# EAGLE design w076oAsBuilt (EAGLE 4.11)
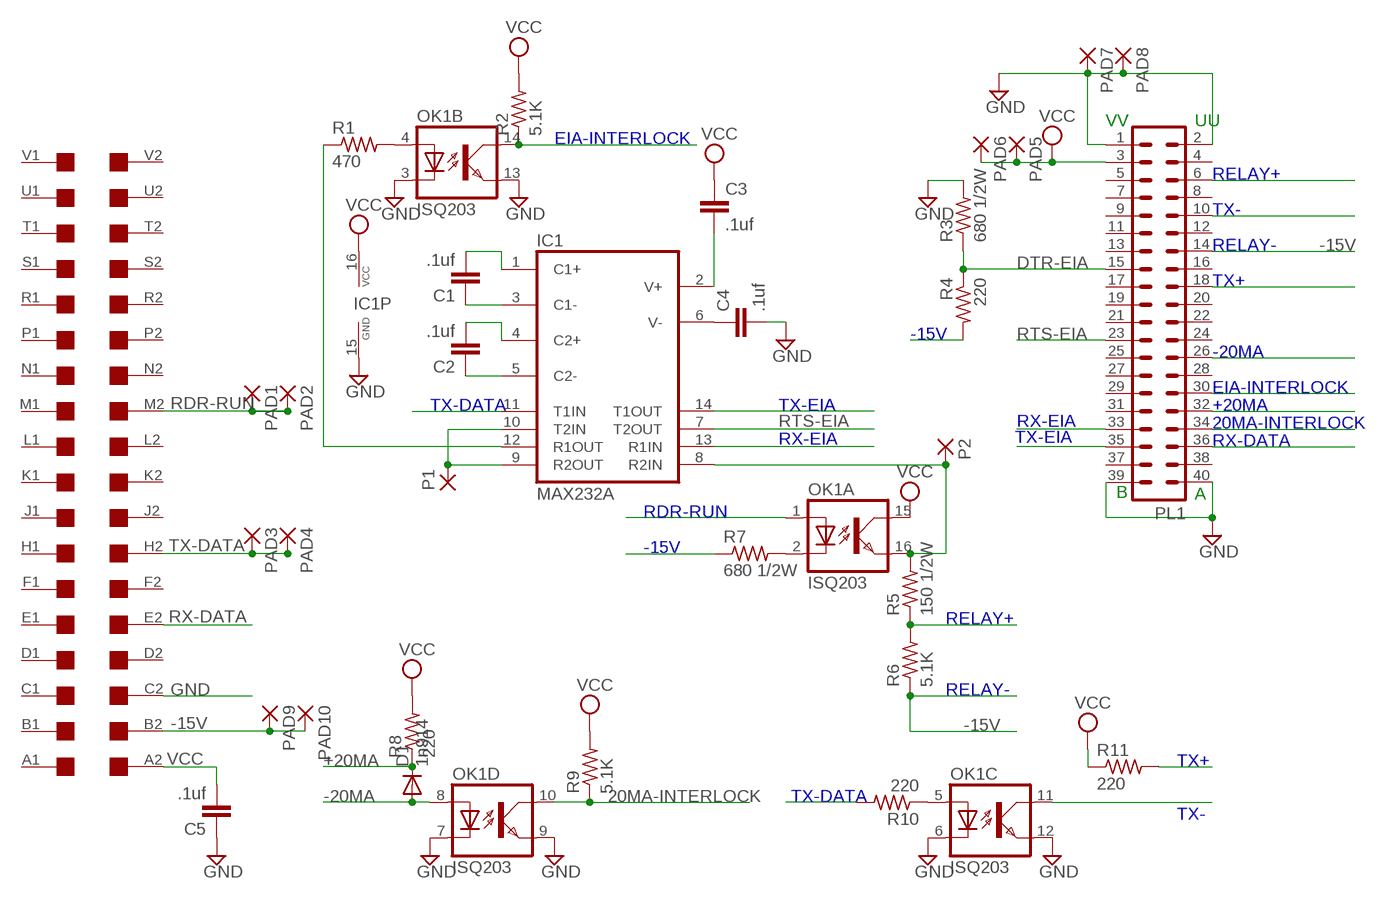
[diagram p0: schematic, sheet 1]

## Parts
C1  .1uf  C-EU050-025X075  [C050-025X075]
C2  .1uf  C-EU050-025X075  [C050-025X075]
C3  .1uf  C-EU050-025X075  [C050-025X075]
C4  .1uf  C-EU050-025X075  [C050-025X075]
C5  .1uf  C-EU050-025X075  [C050-025X075]
D1  1n914  1N4004  [DO41-10]
IC1  MAX232A  MAX232  [DIL16]
OK1  ISQ203  ILQ1  [DIL16]
P1  1,6/0,8  [1,6/0,8]
P2  1,6/0,8  [1,6/0,8]
PAD1  1,6/0,8  [1,6/0,8]
PAD2  1,6/0,8  [1,6/0,8]
PAD3  1,6/0,8  [1,6/0,8]
PAD4  1,6/0,8  [1,6/0,8]
PAD5  1,6/0,8  [1,6/0,8]
PAD6  1,6/0,8  [1,6/0,8]
PAD7  1,6/0,8  [1,6/0,8]
PAD8  1,6/0,8  [1,6/0,8]
PAD9  1,6/0,8  [1,6/0,8]
PAD10  1,6/0,8  [1,6/0,8]
PL1  40H  [40H]
R1  470  R-US_0207/10  [0207/10]
R2  5.1K  R-US_0207/10  [0207/10]
R3  680 1/2W  R-US_0207/12  [0207/12]
R4  220  R-US_0207/10  [0207/10]
R5  150 1/2W  R-US_0207/12  [0207/12]
R6  5.1K  R-US_0207/10  [0207/10]
R7  680 1/2W  R-US_0207/12  [0207/12]
R8  220  R-US_0207/10  [0207/10]
R9  5.1K  R-US_0207/10  [0207/10]
R10  220  R-US_0207/10  [0207/10]
R11  220  R-US_0207/10  [0207/10]
U$1  DEC-FLIPCHIP  [DEC-FLIPCHIP]

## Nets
20MA-INTERLOCK: OK1.10(D:COL) PL1.34 R9.1
+20MA: D1.C PL1.32 R8.1
-15V: PAD9.1(P) PAD10.1(P) PL1.14 R4.2 R6.1 R7.1 U$1.B2
-20MA: D1.A OK1.8(D:A) PL1.26
DTR-EIA: PL1.15 R3.1 R4.1
EIA-INTERLOCK: OK1.14(B:COL) PL1.30 R2.1
GND: C4.2 C5.1 IC1.15(GND) OK1.3(B:C) OK1.6(C:C) OK1.7(D:C) OK1.9(D:EMIT) OK1.12(C:EMIT) OK1.13(B:EMIT) PAD7.1(P) PAD8.1(P) PL1.1 PL1.2 PL1.39 PL1.40 R3.2 U$1.C2
N$1: C2.1 IC1.5(C2-)
N$2: C2.2 IC1.4(C2+)
N$3: C1.2 IC1.1(C1+)
N$4: C1.1 IC1.3(C1-)
N$5: OK1.2(A:C) R7.2
N$6: IC1.9(R2OUT) IC1.10(T2IN) P1.1(P)
N$7: IC1.8(R2IN) OK1.16(A:EMIT) P2.1(P) R5.2
N$8: IC1.12(R1OUT) R1.1
N$9: C3.2 IC1.2(V+)
N$10: C4.1 IC1.6(V-)
N$11: OK1.4(B:A) R1.2
N$15: OK1.5(C:A) R10.1
RDR-RUN: OK1.1(A:A) PAD1.1(P) PAD2.1(P) U$1.M2
RELAY+: PL1.6 R5.1 R6.2
RTS-EIA: IC1.7(T2OUT) PL1.23
RX-DATA: PL1.36 U$1.E2
RX-EIA: IC1.13(R1IN) PL1.33
TX+: PL1.18 R11.2
TX-: OK1.11(C:COL) PL1.10
TX-DATA: IC1.11(T1IN) PAD3.1(P) PAD4.1(P) R10.2 U$1.H2
TX-EIA: IC1.14(T1OUT) PL1.35
VCC: C3.1 C5.2 IC1.16(VCC) OK1.15(A:COL) PAD5.1(P) PAD6.1(P) PL1.3 R2.2 R8.2 R9.2 R11.1 U$1.A2
Unconnected: PL1.4 PL1.5 PL1.7 PL1.8 PL1.9 PL1.11 PL1.12 PL1.13 PL1.16 PL1.17 PL1.19 PL1.20 PL1.21 PL1.22 PL1.24 PL1.25 PL1.27 PL1.28 PL1.29 PL1.31 PL1.37 PL1.38 U$1.A1 U$1.B1 U$1.C1 U$1.D1 U$1.D2 U$1.E1 U$1.F1 U$1.F2 U$1.H1 U$1.J1 U$1.J2 U$1.K1 U$1.K2 U$1.L1 U$1.L2 U$1.M1 U$1.N1 U$1.N2 U$1.P1 U$1.P2 U$1.R1 U$1.R2 U$1.S1 U$1.S2 U$1.T1 U$1.T2 U$1.U1 U$1.U2 U$1.V1 U$1.V2

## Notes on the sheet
- VV | UU
- EIA-INTERLOCK
- RELAY+
- TX-
- RELAY-
- TX+
- -15V
- -20MA
- EIA-INTERLOCK
- TX-DATA | TX-EIA | +20MA
- RX-EIA | 20MA-INTERLOCK
- RX-EIA | TX-EIA | RX-DATA
- B | A
- RDR-RUN
- -15V
- RELAY+
- RELAY-
- TX+
- TX-DATA
- TX-

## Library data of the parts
C1-C5 = rcl:C-EU: CAPACITOR, European symbol
D1 = diode:1N4004: DIODE
IC1 = maxim:MAX232: RS232 TRANSEIVER
OK1 = optocoupler:ILQ1: SIEMENS OPTO COUPLER
P1 P2 PAD1-PAD10 = wirepad:1,6/0,8: THROUGH-HOLE PAD
PL1 = con-harting-h:40H: CONNECTOR
R1-R11 = rcl:R-US_: RESISTOR, American symbol
U$1 = con-dec:DEC-FLIPCHIP: DEC Flip-Chip single card fingers

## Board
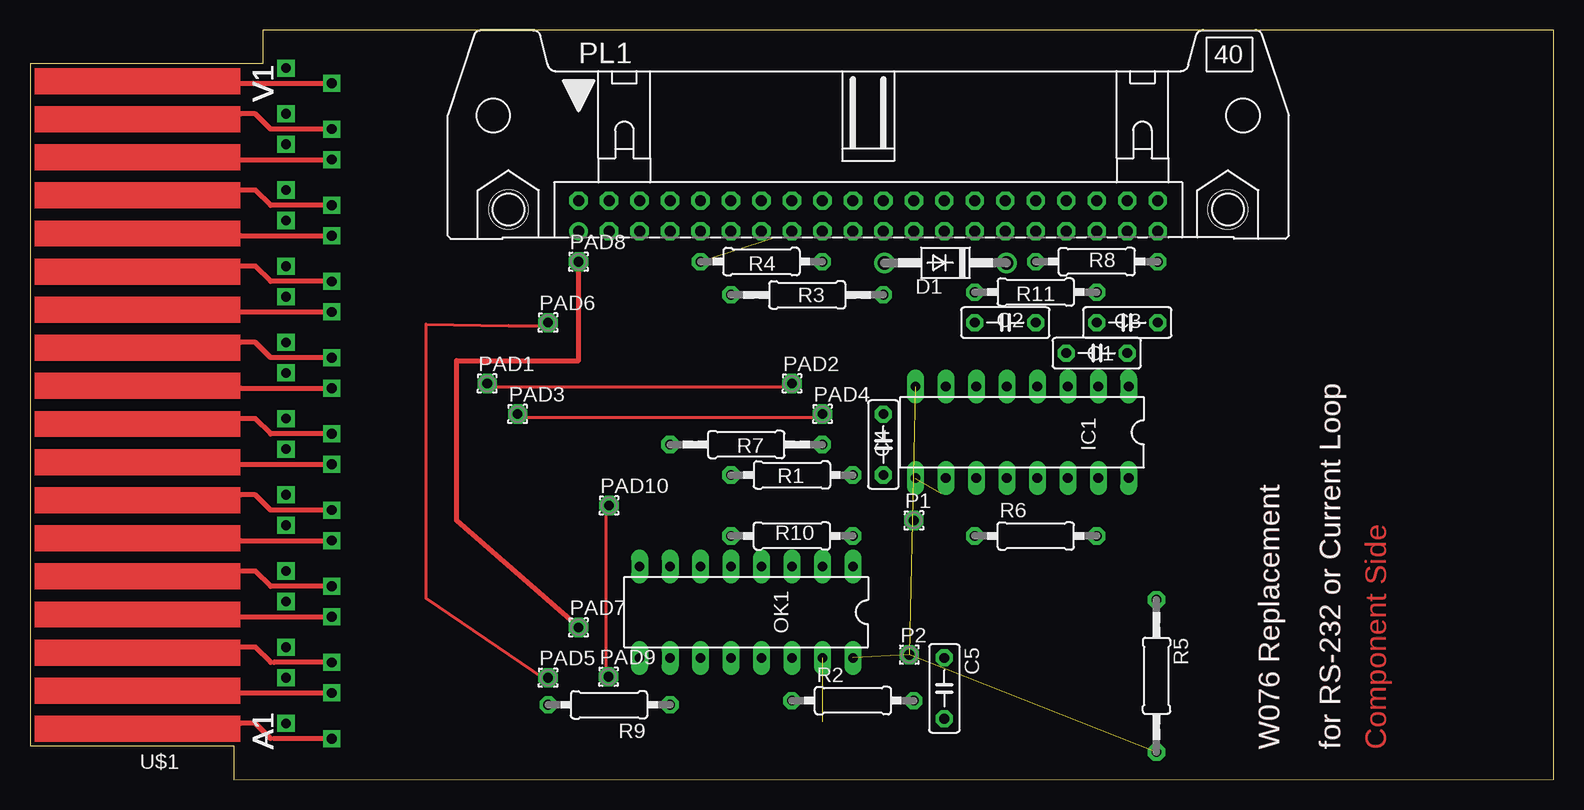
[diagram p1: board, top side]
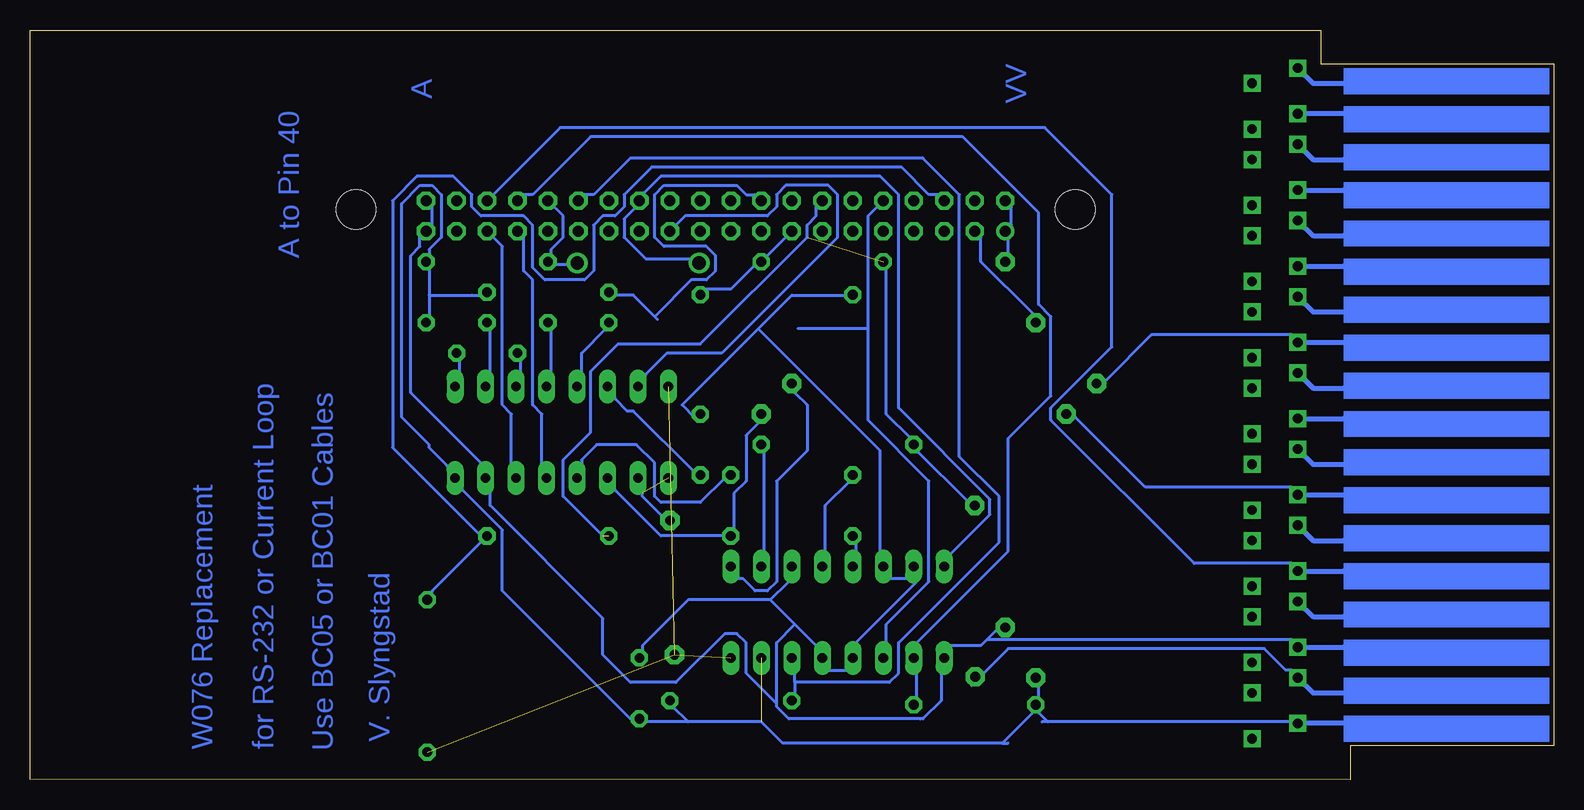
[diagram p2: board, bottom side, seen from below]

Size 126.98 x 62.48 mm. Coordinates in mm from the lower left corner, seen from the top.
Outline: 0,2.83 16.96,2.83 16.96,0 126.98,0.04 126.98,62.45 19.4,62.48 19.4,59.65 0,59.65 0,2.83
Copper layers (1*16): Top 0.035mm / dielectric 1.5mm / Bottom 0.035mm
Design rules "10mils": minimum track width 10mil, minimum drill 28mil, track to track 15mil, track to pad 10mil, pad to pad 10mil, via to via 10mil, smd to smd 10mil, copper to edge 40mil, drill to drill 10mil, minimum pad ring 12mil, minimum via ring 8mil, stop-mask expansion 0mil, vias tented up to drill 0mil, thermal gap 10mil

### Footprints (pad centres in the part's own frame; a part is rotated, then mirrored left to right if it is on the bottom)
C050-025X075 = drill 0.813 octagon: 1 -2.54,0; 2 2.54,0
DO41-10 = drill 1.118 round: A 5.08,0; C -5.08,0
DIL16 = drill 0.813 long: 1 -8.89,-3.81; 2 -6.35,-3.81; 3 -3.81,-3.81; 4 -1.27,-3.81; 5 1.27,-3.81; 6 3.81,-3.81; 7 6.35,-3.81; 8 8.89,-3.81; 9 8.89,3.81; 10 6.35,3.81; 11 3.81,3.81; 12 1.27,3.81; 13 -1.27,3.81; 14 -3.81,3.81; 15 -6.35,3.81; 16 -8.89,3.81
1,6/0,8 = drill 0.813 pad 1.6 octagon: 1 0,0
40H = drill 0.914 round: 1 -24.13,-1.27 | drill 0.914 octagon: 2 -24.13,1.27; 3 -21.59,-1.27; 4 -21.59,1.27; 5 -19.05,-1.27; 6 -19.05,1.27; 7 -16.51,-1.27; 8 -16.51,1.27; 9 -13.97,-1.27; 10 -13.97,1.27; 11 -11.43,-1.27; 12 -11.43,1.27; 13 -8.89,-1.27; 14 -8.89,1.27; 15 -6.35,-1.27; 16 -6.35,1.27; 17 -3.81,-1.27; 18 -3.81,1.27; 19 -1.27,-1.27; 20 -1.27,1.27; 21 1.27,-1.27; 22 1.27,1.27; 23 3.81,-1.27; 24 3.81,1.27; 25 6.35,-1.27; 26 6.35,1.27; 27 8.89,-1.27; 28 8.89,1.27; 29 11.43,-1.27; 30 11.43,1.27; 31 13.97,-1.27; 32 13.97,1.27; 33 16.51,-1.27; 34 16.51,1.27; 35 19.05,-1.27; 36 19.05,1.27; 37 21.59,-1.27; 38 21.59,1.27; 39 24.13,-1.27; 40 24.13,1.27 | hole 3.302: -29.972,0.533; 29.972,0.533
0207/10 = drill 0.813 octagon: 1 -5.08,0; 2 5.08,0
0207/12 = drill 0.813 octagon: 1 -6.35,0; 2 6.35,0
DEC-FLIPCHIP = drill 0.813 square: A1 -7.62,27.94; A2 -3.81,26.67; B1 -7.62,24.13; B2 -3.81,22.86; C1 -7.62,21.59; C2 -3.81,20.32; D1 -7.62,17.78; D2 -3.81,16.51; E1 -7.62,15.24; E2 -3.81,13.97; F1 -7.62,11.43; F2 -3.81,10.16; H1 -7.62,8.89; H2 -3.81,7.62; J1 -7.62,5.08; J2 -3.81,3.81; K1 -7.62,2.54; K2 -3.81,1.27; L1 -7.62,-1.27; L2 -3.81,-2.54; M1 -7.62,-3.81; M2 -3.81,-5.08; N1 -7.62,-7.62; N2 -3.81,-8.89; P1 -7.62,-10.16; P2 -3.81,-11.43; R1 -7.62,-13.97; R2 -3.81,-15.24; S1 -7.62,-16.51; S2 -3.81,-17.78; T1 -7.62,-20.32; T2 -3.81,-21.59; U1 -7.62,-22.86; U2 -3.81,-24.13; V1 -7.62,-26.67; V2 -3.81,-27.94

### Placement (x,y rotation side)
C1  88.9,35.56 0 top
C2  81.28,38.1 0 top
C3  91.44,38.1 180 top
C4  71.12,27.94 90 top
C5  76.2,7.62 270 top
D1  76.3,43.08 180 top
IC1  82.67,28.96 180 top
OK1  59.68,13.97 180 top
P1  73.66,21.62 0 top
P2  73.27,10.41 0 top
PAD1  38.09,33.02 0 top
PAD2  63.49,33.02 0 top
PAD3  40.63,30.48 0 top
PAD4  66.04,30.48 0 top
PAD5  43.17,8.51 0 top
PAD6  43.17,38.1 0 top
PAD7  45.71,12.7 0 top
PAD8  45.71,43.18 0 top
PAD9  48.2,8.59 0 top
PAD10  48.25,22.86 0 top
PL1  69.84,46.99 0 top
R1  63.49,25.4 180 top
R2  68.58,6.6 0 top
R3  64.77,40.41 180 top
R4  60.95,43.18 180 top
R5  93.87,8.66 270 top
R6  83.81,20.32 0 top
R7  59.68,27.94 0 top
R8  88.9,43.18 0 top
R9  48.25,6.25 180 top
R10  63.49,20.32 0 top
R11  83.81,40.64 180 top
U$1  17.52,31.37 180 top

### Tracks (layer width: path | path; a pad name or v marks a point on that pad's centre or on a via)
20MA-INTERLOCK
  Bottom 0.254: PL1.34 85.85,48.77 85.09,48.77 80.26,53.59 49.27,53.59 42.92,47.24 42.92,39.62 41.9,38.61 41.9,32 45.46,28.45 45.46,19.05 53.08,11.43 OK1.10 53.08,8.89 53.08,6.86 R9.1
+20MA
  Bottom 0.254: PL1.32 82.55,46.99 82.55,45.21 83.56,44.2 83.56,43.69 R8.1 83.31,42.93 82.04,42.93 D1.C
-15V  (2 unrouted)
  Top 0.254: PAD9.1 48,8.38 48,22.1 PAD10.1
  Bottom 0.254: PAD10.1 48.76,23.11 53.08,27.43 R7.1 53.59,28.45 55.62,30.48 55.62,42.67 R4.2 | U$1.B2 21.84,9.14 22.35,9.14 24.12,10.92 45.46,10.92 47.49,8.89 PAD9.1 | PAD9.1 48.76,8.13 | PAD9.1 48.51,7.87 | 78.23,20.07 R6.1 78.48,19.81 | 79.24,20.32 82.55,23.62 82.55,26.67 80.26,28.96 80.26,34.04 77.97,36.32 71.12,36.32 62.22,45.21 62.22,46.23 61.46,46.99 61.46,47.75 PL1.14
-20MA
  Bottom 0.254: OK1.8 50.29,18.8 46.98,22.1 46.98,23.37 54.6,30.99 54.6,48.77 56.13,50.29 74.42,50.29 75.94,48.77 PL1.26 76.45,47.75 77.47,46.74 77.47,45.21 75.69,43.43 71.88,43.43 D1.A
DTR-EIA
  Bottom 0.254: PL1.15 R4.1 66.54,42.93 68.58,40.89 70.61,40.89 R3.1
EIA-INTERLOCK
  Bottom 0.254: 63.24,8.13 63.24,8.89 OK1.14 | 63.24,8.13 55.37,8.13 54.6,8.89 54.6,11.43 46.22,19.81 46.22,23.62 49.52,26.92 49.52,48.77 52.57,51.82 76.96,51.82 80.01,48.77 80.77,48.77 PL1.30 | 63.24,8.13 63.24,7.11 R2.1
GND
  Top 0.406: PAD8.1 45.71,34.92 35.55,34.92 35.55,21.59 PAD7.1
  Bottom 0.254: 70.61,30.23 C4.2 71.62,30.23 72.64,31.24 66.29,37.59 | 47.24,11.68 46.48,12.45 PAD7.1 | 47.24,11.68 47.75,11.18 50.29,11.18 OK1.9 51.05,8.89 51.05,6.6 52.57,5.08 52.83,5.08 | 47.24,11.68 21.84,11.68 U$1.C2 | PL1.40 93.47,47.75 93.47,46.23 PL1.39 94.48,45.21 94.48,44.45 95.25,43.69 95.25,32.26 89.4,26.42 IC1.15 88.64,23.88 88.64,22.86 79.24,13.46 79.24,10.41 76.96,8.13 73.15,8.13 69.08,12.19 68.07,12.19 67.31,11.43 67.31,8.89 64.77,6.35 | PAD8.1 45.46,43.94 45.46,45.21 PL1.1 45.21,46.23 45.21,47.75 PL1.2 | 66.29,37.59 63.49,40.39 58.92,40.39 R3.2 | 66.29,37.59 56.13,27.43 56.13,19.05 OK1.6 55.37,16.76 53.84,16.76 OK1.7 53.08,16.51 58.16,11.43 OK1.12 58.92,9.14 60.45,9.14 OK1.13 61.46,11.18 63.24,12.95 | 65.27,14.99 72.13,14.99 75.94,11.18 75.94,10.67 C5.1 | 65.27,14.99 63.75,16.51 OK1.3 | 63.24,12.95 65.27,14.99 | 63.24,12.95 64.77,11.43 64.77,6.35 | 64.77,6.35 64.77,6.1 63.75,5.08 52.83,5.08 | 52.83,5.08 52.75,5.11
N$1
  Bottom 0.254: IC1.5 81.02,34.04 81.02,35.56 78.99,37.59 C2.1
N$2
  Bottom 0.254: IC1.4 83.56,34.04 83.56,37.59 C2.2
N$3
  Bottom 0.254: IC1.1 91.18,34.04 91.18,35.05 C1.2
N$4
  Bottom 0.254: IC1.3 86.1,34.04 86.1,35.05 C1.1
N$5
  Bottom 0.254: OK1.2 65.78,19.05 65.78,27.43 R7.2
N$6  (1 unrouted)
  Bottom 0.254: IC1.10 75.94,23.88 75.94,23.62 74.16,21.84 P1.1
N$7  (3 unrouted)
N$8
  Bottom 0.254: IC1.12 81.02,26.42 81.02,26.67 79.75,27.94 76.45,27.94 74.93,26.42 74.93,23.62 74.42,23.11 71.12,23.11 69.08,25.15 R1.1
N$9
  Bottom 0.254: IC1.2 88.64,34.04 88.64,37.59 C3.2
N$10
  Bottom 0.254: C4.1 71.62,25.65 76.7,30.73 77.21,30.73 78.23,31.75 IC1.6
N$11
  Bottom 0.254: OK1.4 60.7,19.05 60.7,22.86 58.67,24.89 R1.2
N$15
  Bottom 0.254: OK1.5 58.16,19.05 58.16,19.81 R10.1
RDR-RUN
  Top 0.254: PAD1.1 38.86,32.77 62.73,32.77 PAD2.1
  Bottom 0.254: U$1.M2 21.84,37.08 33.52,37.08 37.33,33.27 PAD1.1 | OK1.1 68.07,16.76 67.56,16.76 66.54,15.75 65.53,15.75 64.77,16.51 64.77,24.89 62.22,27.43 62.22,31.24 63.24,32.26 PAD2.1
RELAY+
  Bottom 0.254: R6.2 89.4,20.07 | PL1.6 51.3,48.77 52.06,48.77 54.35,51.05 75.18,51.05 77.47,48.77 77.47,47.75 78.23,46.99 79.24,46.99 80.01,46.23 80.01,42.42 80.77,41.66 84.07,41.66 85.09,42.67 85.09,46.23 85.85,46.99 89.4,46.99 90.17,47.75 90.17,48.77 91.69,50.29 94.74,50.29 96.77,48.26 96.77,27.69 89.4,20.32 R6.2 | R5.1 93.47,15.75 R6.2
RTS-EIA
  Bottom 0.254: IC1.7 75.69,33.78 73.91,35.56 69.34,35.56 59.68,45.21 59.68,48.77 60.45,49.53 64,49.53 64.77,48.77 64.77,47.75 65.53,46.99 72.39,46.99 PL1.23
RX-DATA
  Bottom 0.254: U$1.E2 21.84,18.03 29.97,18.03 41.9,29.97 41.9,30.99 36.82,36.07 36.82,48.77 42.41,54.36 82.8,54.36 PL1.36
RX-EIA
  Bottom 0.254: IC1.13 84.32,26.42 84.32,30.48 85.09,31.24 85.09,41.66 85.85,42.42 85.85,45.21 PL1.33
TX+
  Bottom 0.254: 74.93,38.61 74.67,38.35 | 74.93,38.61 76.7,40.39 78.23,40.39 R11.2 | 74.93,38.61 71.88,41.66 70.61,41.66 69.84,42.42 69.84,43.69 70.61,44.45 74.16,44.45 74.93,45.21 74.93,48.77 74.16,49.53 68.07,49.53 67.31,48.77 66.54,48.77 PL1.18
TX-
  Bottom 0.254: 57.14,37.59 57.14,29.97 52.06,24.89 52.06,16.51 55.62,12.95 55.62,11.43 OK1.11 | 57.14,37.59 57.14,46.99 PL1.10 | 57.14,37.59 62.99,37.59
TX-DATA
  Top 0.254: PAD4.1 65.27,30.23 41.4,30.23 PAD3.1
  Bottom 0.254: R10.2 69.08,20.57 | U$1.H2 21.84,24.38 34.03,24.38 39.87,30.23 PAD3.1 | R10.2 68.32,20.83 68.32,23.88 67.31,24.89 67.31,28.7 66.29,29.72 PAD4.1 | IC1.11 78.23,24.13 74.42,20.32 R10.2
TX-EIA
  Bottom 0.254: IC1.14 86.86,26.42 86.86,30.48 87.62,31.24 87.62,44.45 PL1.35
VCC  (1 unrouted)
  Top 0.254: PAD6.1 42.41,37.85 39.87,37.85 33.02,37.97 33.02,15.11 42.92,8.38 PAD5.1
  Bottom 0.254: 42.16,4.83 21.84,4.83 U$1.A2 | 42.16,4.83 42.67,4.83 | 93.72,40.39 93.72,42.67 R8.2 93.72,43.69 93.72,44.2 92.7,45.21 92.7,48.77 93.47,49.53 94.48,49.53 96.01,48.01 96.01,30.23 93.72,27.94 93.72,27.69 92.2,26.16 IC1.16 90.93,24.13 87.62,20.83 87.62,15.75 76.7,4.83 C5.2 | 93.72,40.39 93.72,38.61 C3.1 | 93.72,40.39 90.17,40.39 89.4,40.39 R11.1 | C5.2 75.69,4.83 72.13,4.83 | PL1.3 47.75,45.21 47.75,43.18 43.43,38.86 PAD6.1 | 45.97,3.05 45.46,3.05 | 45.97,3.05 64.26,3.05 66.04,4.83 72.13,4.83 | 42.16,4.83 42.92,5.59 R9.2 | R9.2 42.92,6.86 42.92,7.87 PAD5.1 | 45.97,3.05 43.43,5.59 R9.2 | C5.2 76.45,5.59 | 72.13,4.83 73.4,6.1 R2.2

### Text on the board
Top: W076 Replacement | for RS-232 or Current Loop | Component Side
Bottom: VV | A | A to Pin 40 | V. Slyngstad | for RS-232 or Current Loop | W076 Replacement | Use BC05 or BC01 Cables
tPlace: W076 Replacement | for RS-232 or Current Loop
tNames: V1 | V1 | V1 | V1 | V1 | V1 | V1 | V1 | V1 | V1 | V1 | V1 | V1 | V1 | V1 | V1 | V1 | V1 | V1 | V1 | V1 | V1 | V1 | V1 | V1 | V1 | V1 | V1 | V1 | V1 | V1 | V1 | A1 | A1 | A1 | A1 | A1 | A1 | A1 | A1 | A1 | A1 | A1 | A1 | A1 | A1 | A1 | A1 | A1 | A1 | A1 | A1 | A1 | A1 | A1 | A1 | A1 | A1 | A1 | A1 | A1 | A1 | A1 | A1
_tplace: 1n914 | 220 | 220 | 220 | MAX232A | 680 1/2W | 220 | 220 | 5.1K | ISQ203 | .1uf | 5.1K | 5.1K
_layer121: PL1 | PL1 | 40 | 40 | V1 | V1 | V1 | V1 | V1 | V1 | V1 | V1 | V1 | V1 | V1 | V1 | V1 | V1 | V1 | V1 | V1 | V1 | V1 | V1 | V1 | V1 | V1 | V1 | V1 | V1 | V1 | V1 | V1 | V1 | V1 | V1 | V1 | V1 | V1 | V1 | V1 | V1 | V1 | V1 | V1 | V1 | V1 | V1 | V1 | V1 | V1 | V1 | V1 | V1 | V1 | V1 | V1 | V1 | V1 | V1 | V1 | V1 | V1 | V1 | V1 | V1 | V1 | V1 | 1n914 | 1n914 | R8 | R8 | PAD8 | PAD8 | 220 | 220 | 220 | 220 | R4 | R4 | 680 1/2W | 680 1/2W | 1n914 | 1n914 | D1 | D1 | 220 | 220 | .1uf | .1uf | C2 | C2 | PAD6 | PAD6 | R3 | R3 | R11 | R11 | C1 | C1 | D2 | D2 | C3 | C3 | .1uf | .1uf | PAD1 | PAD1 | PAD2 | PAD2 | .1uf | .1uf | IC1 | IC1 | PAD3 | PAD3 | PAD4 | PAD4 | MAX232A | MAX232A | R7 | R7 | 680 1/2W | 680 1/2W | 220 | 220 | C4 | C4 | .1uf | .1uf | PAD10 | PAD10 | R1 | R1 | R10 | R10 | R6 | R6 | 220 | 220 | 5.1K | 5.1K | 150 1/2W | 150 1/2W | 1n914 | 1n914 | D4 | D4 | R5 | R5 | OK1 | OK1 | ISQ203 | ISQ203 | PAD7 | PAD7 | .1uf | .1uf | C5 | C5 | PAD5 | PAD5 | PAD9 | PAD9 | R2 | R2 | 5.1K | 5.1K | 5.1K | 5.1K | R9 | R9 | A1 | A1 | A1 | A1 | A1 | A1 | A1 | A1 | A1 | A1 | A1 | A1 | A1 | A1 | A1 | A1 | A1 | A1 | A1 | A1 | A1 | A1 | A1 | A1 | A1 | A1 | A1 | A1 | A1 | A1 | A1 | A1 | A1 | A1 | A1 | A1 | A1 | A1 | A1 | A1 | A1 | A1 | A1 | A1 | A1 | A1 | A1 | A1 | A1 | A1 | A1 | A1 | A1 | A1 | A1 | A1 | A1 | A1 | A1 | A1 | A1 | A1 | A1 | A1 | W076 Replacement | W076 Replacement | for RS-232 or Current Loop | for RS-232 or Current Loop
